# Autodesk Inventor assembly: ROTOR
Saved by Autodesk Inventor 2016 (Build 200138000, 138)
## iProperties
Created: 2013-12
Part Number: ROTOR
Material: Générique
Document SubType Name: Assembly
Designer: Bruno
Author: Bruno
Sending System: SolidWorks 2013
Last Author: christophe
Last Saved: 2014-02-15
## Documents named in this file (3)
- D:\Cours\Systèmes\SI\Robot Haptique\Documentations_pedagogique\Modèle solidworks\Réel\ROTOR.iam
- D:\Cours\Systèmes\SI\Robot Haptique\Documentations_pedagogique\Modèle solidworks\Réel\ROTOR.ipt
- D:\Cours\Systèmes\SI\Robot Haptique\Documentations_pedagogique\Modèle solidworks\Réel\ROUE CODEUSE.ipt
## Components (2 placed, 2 different names)
1. ROTOR:1
2. ROUE CODEUSE:1
